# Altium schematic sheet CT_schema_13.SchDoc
size 564 x 458 mm
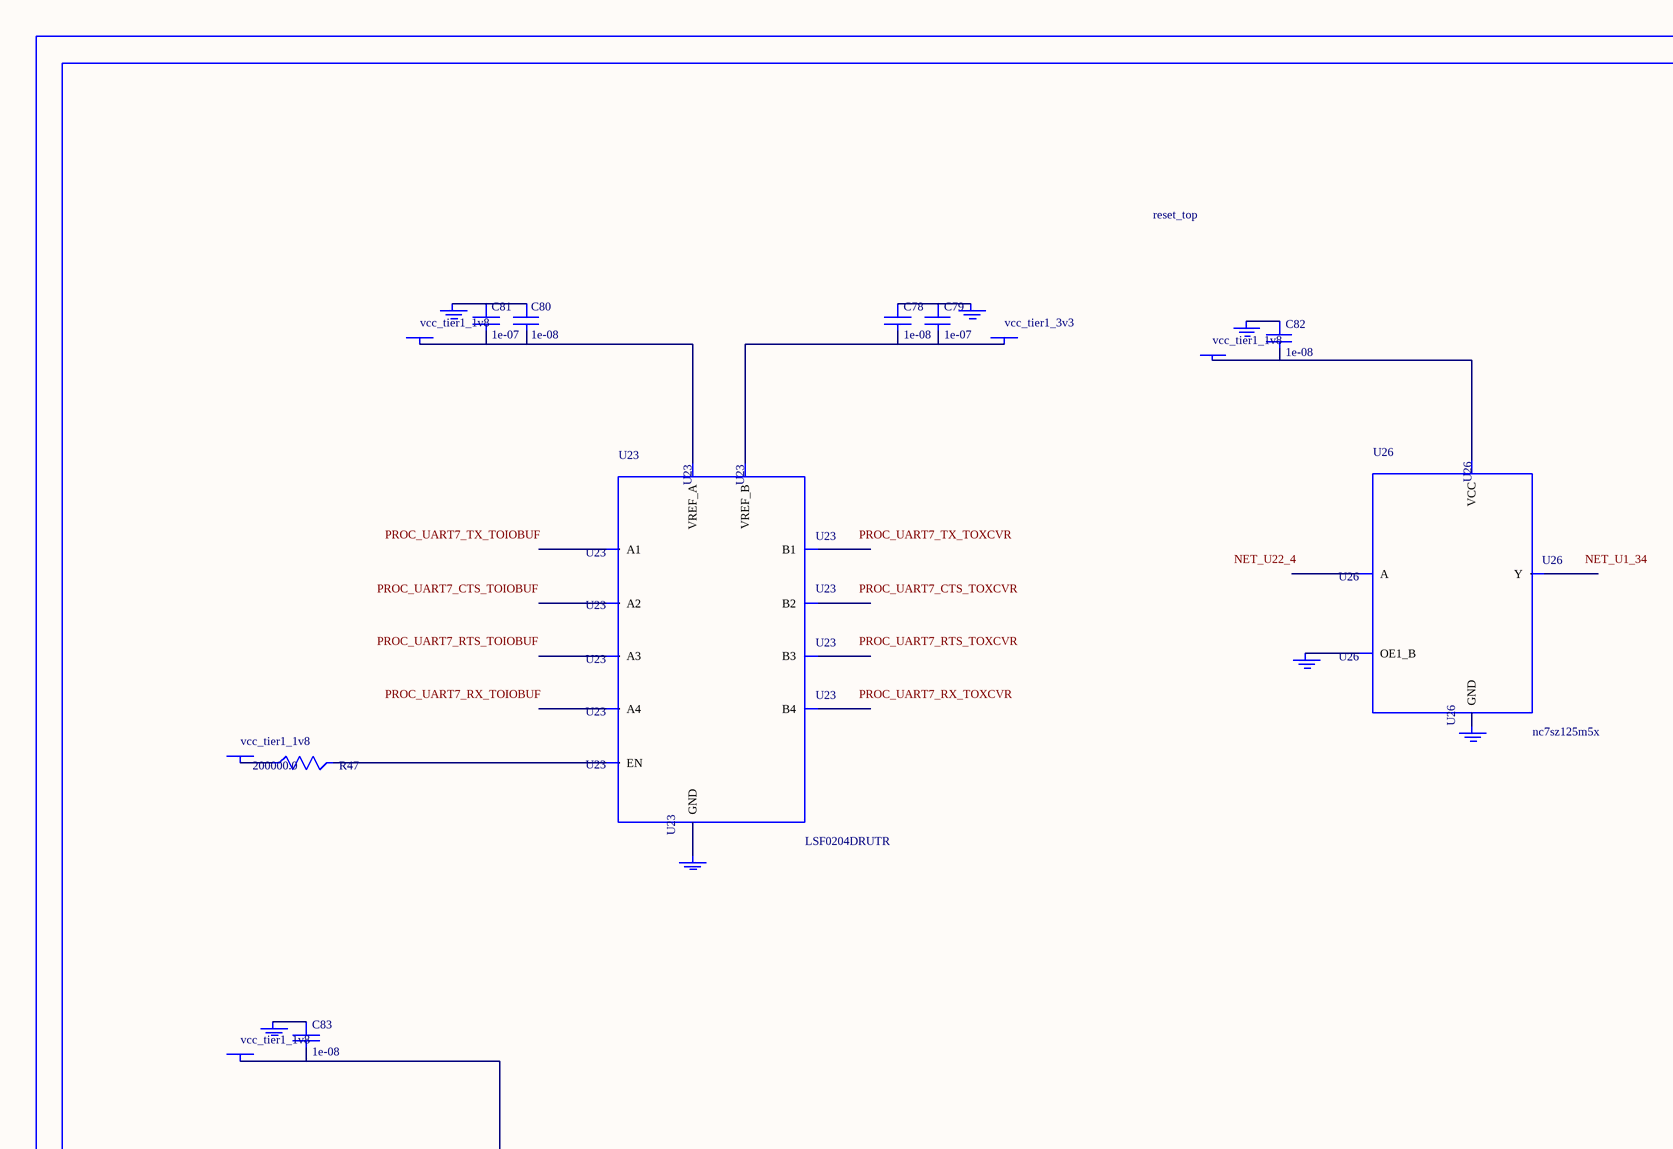
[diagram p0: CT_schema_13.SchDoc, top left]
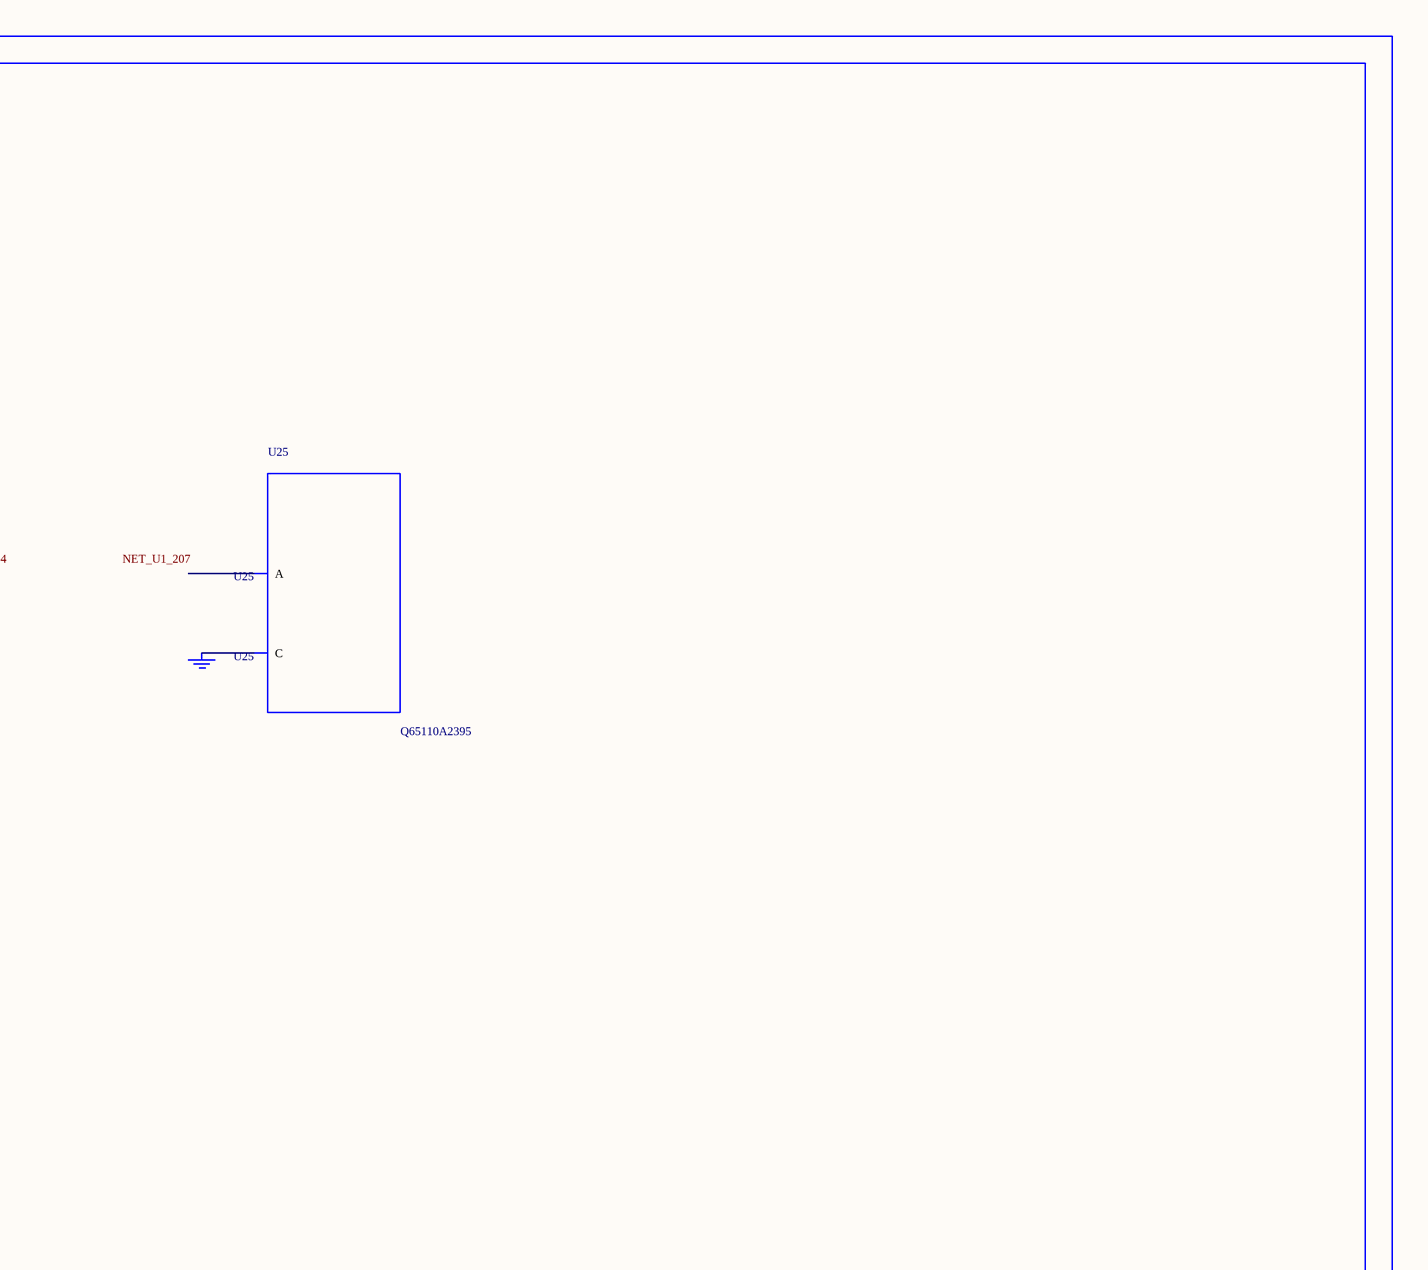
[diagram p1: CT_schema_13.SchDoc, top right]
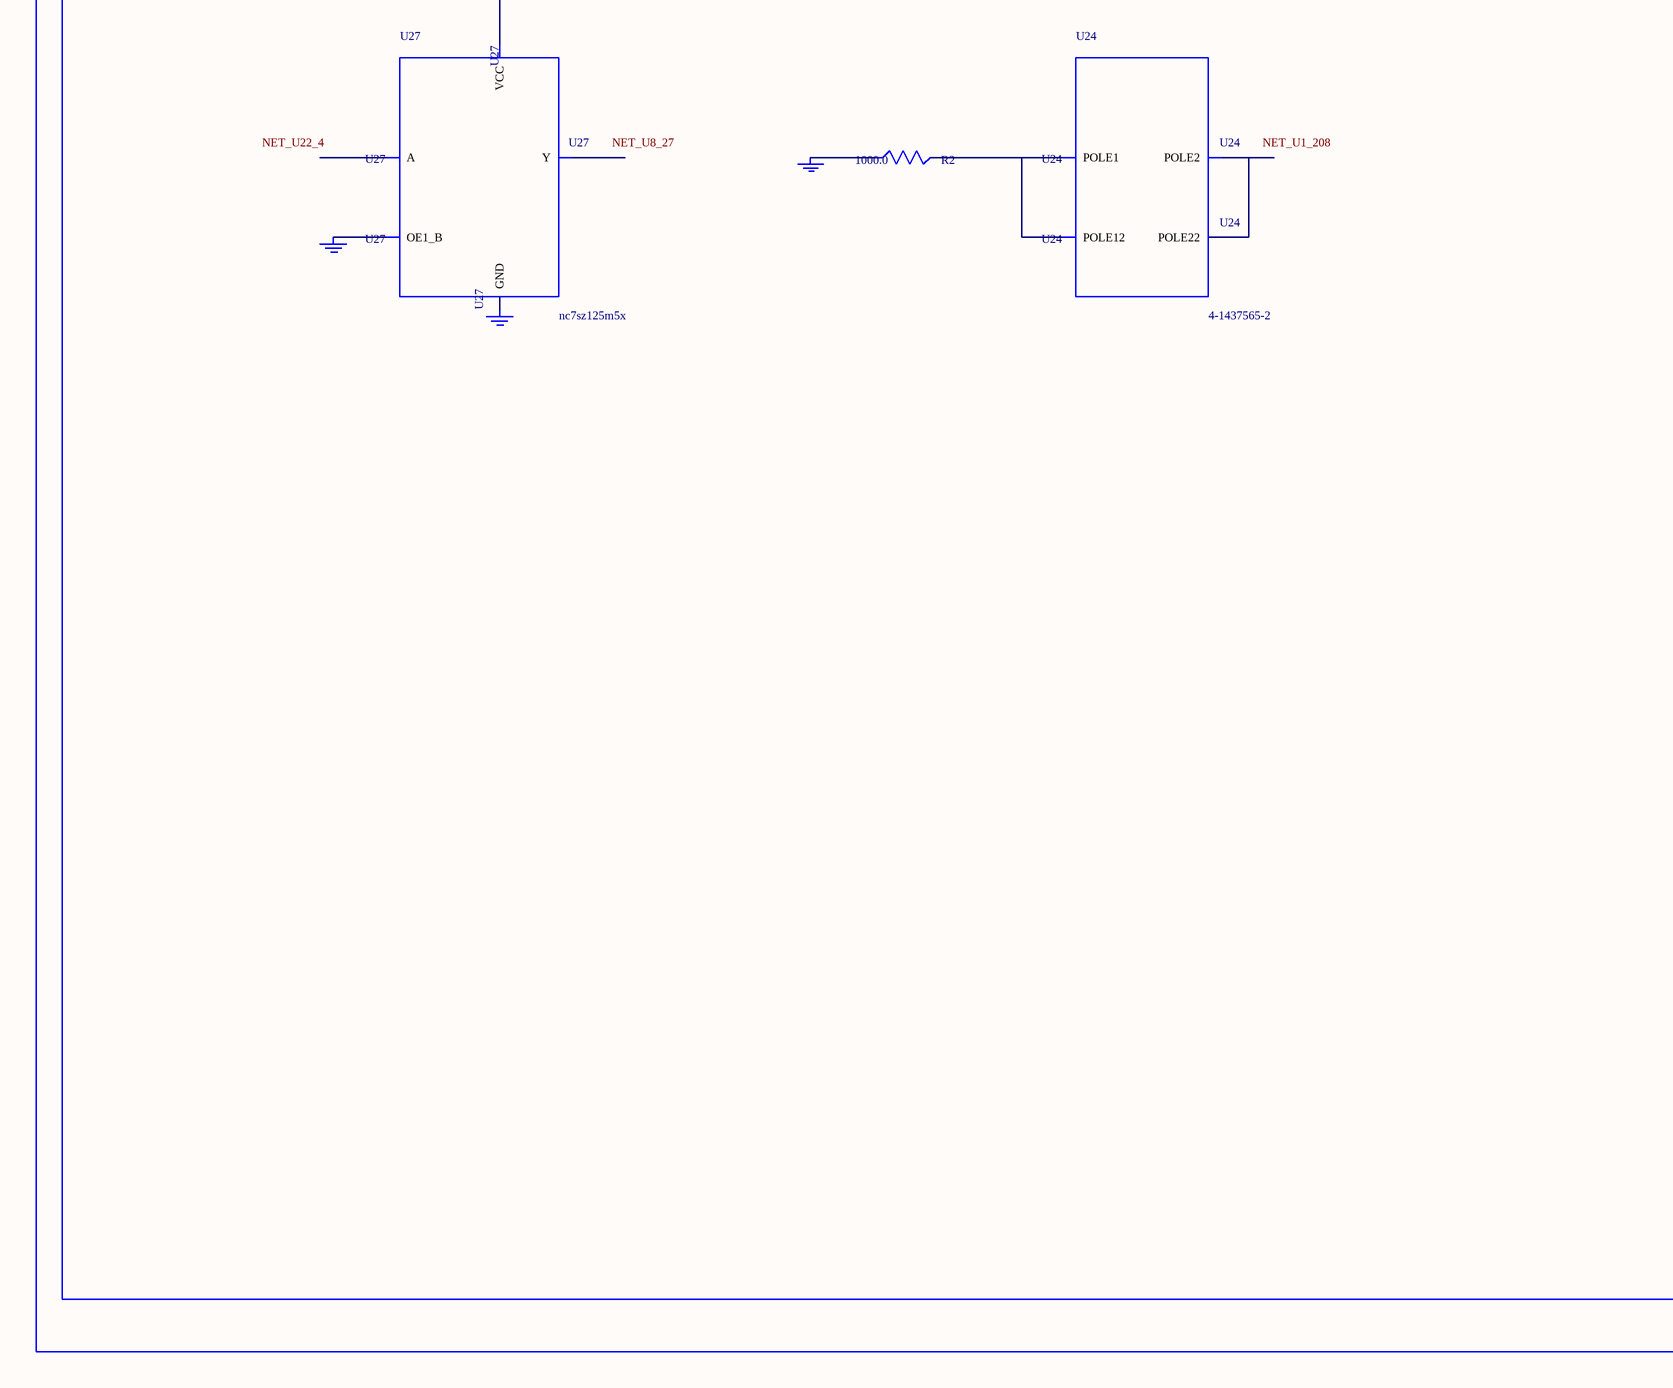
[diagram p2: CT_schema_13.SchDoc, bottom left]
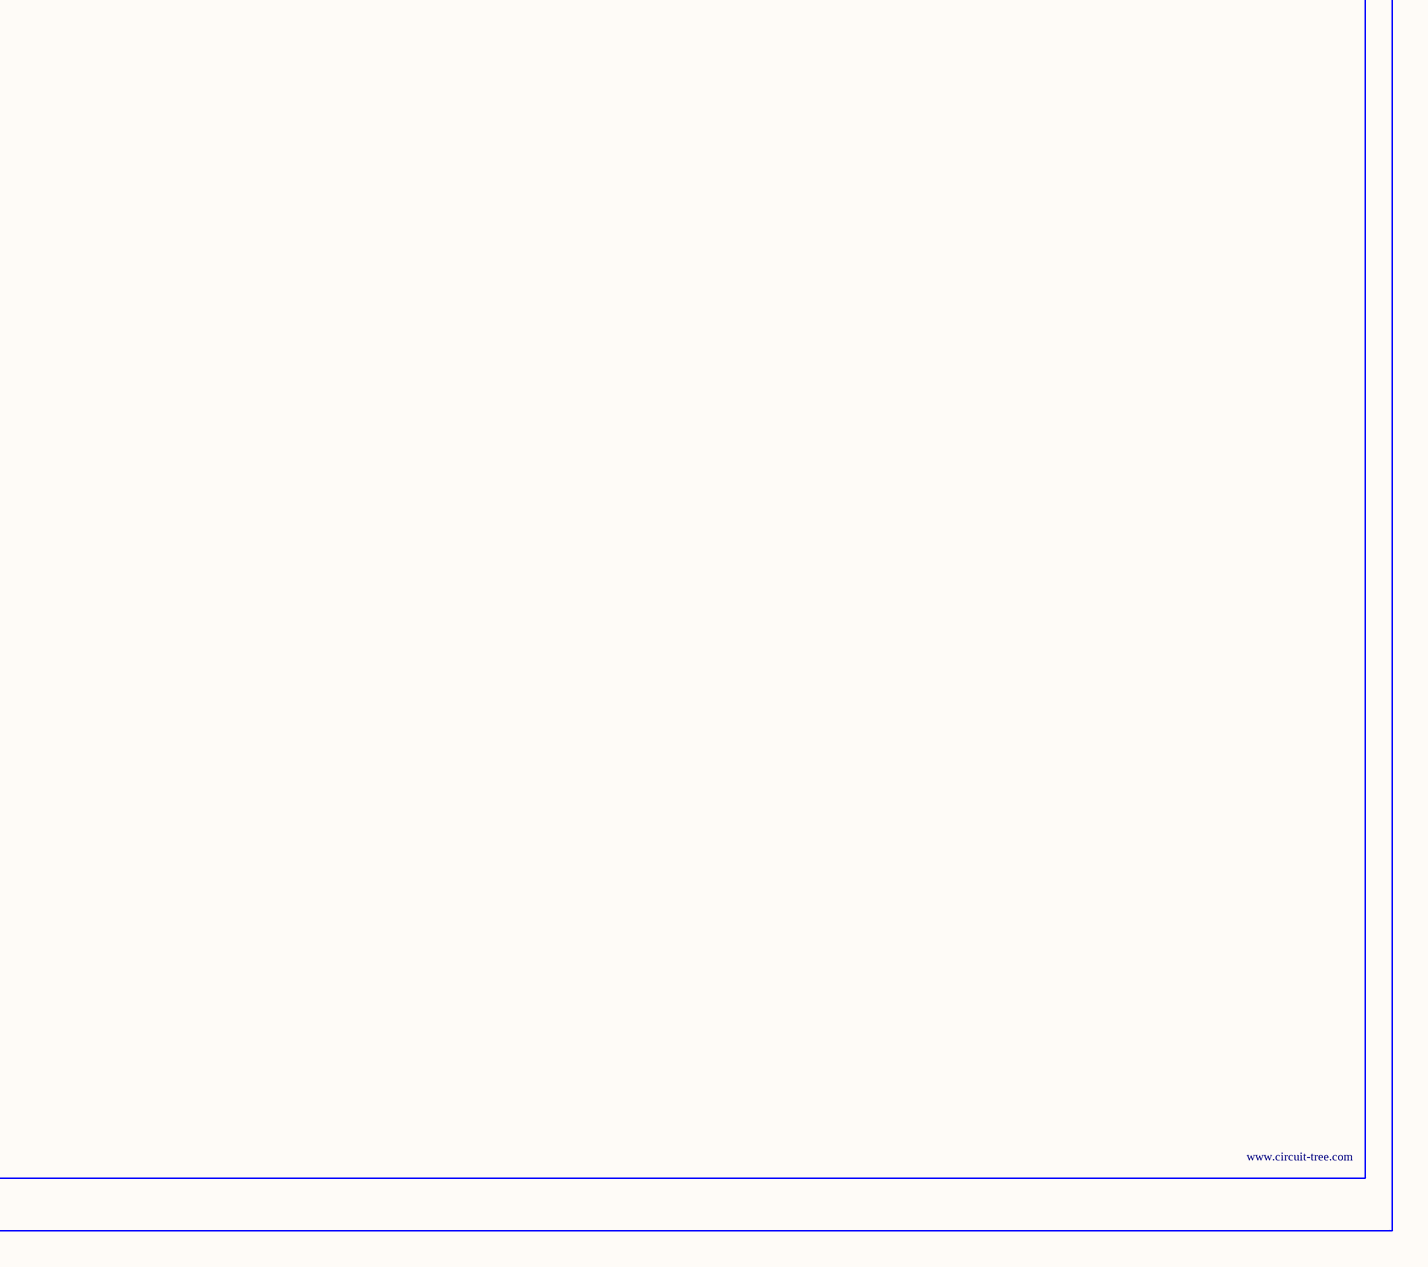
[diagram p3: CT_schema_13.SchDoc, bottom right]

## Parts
BORDER12  (no value)
C78  1e-08  [C0402]
C79  1e-07  [C0402]
C80  1e-08  [C0402]
C81  1e-07  [C0402]
C82  1e-08  [C0402]
C83  1e-08  [C0402]
GND_INSTANCE_12_0  (no value)
GND_INSTANCE_12_1  (no value)
GND_INSTANCE_12_2  (no value)
GND_INSTANCE_12_3  (no value)
GND_INSTANCE_12_4  (no value)
GND_INSTANCE_12_5  (no value)
GND_INSTANCE_12_6  (no value)
GND_INSTANCE_12_7  (no value)
GND_INSTANCE_12_8  (no value)
GND_INSTANCE_12_9  (no value)
GND_INSTANCE_12_10  (no value)
POWER_INSTANCE_12_0  vcc_tier1_1v8
POWER_INSTANCE_12_1  vcc_tier1_3v3
POWER_INSTANCE_12_2  vcc_tier1_1v8
POWER_INSTANCE_12_3  vcc_tier1_1v8
POWER_INSTANCE_12_4  vcc_tier1_1v8
R2  1000.0  [R0603]
R47  200000.0  [R0603]
U23  LSF0204DRUTR  [RUT0012A]
U24  4-1437565-2  [SW_4-1437565-2]
U25  Q65110A2395  [LGM67K-G1J2-24-Z]
U26  nc7sz125m5x  [NC7SZ125M5X]
U27  nc7sz125m5x  [NC7SZ125M5X]

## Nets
NetC78_1: C78.1 C79.1 GND_INSTANCE_12_1.0(GND)
NetC78_2: C78.2 C79.2 POWER_INSTANCE_12_1.0(PWR) U23.11(VREF_B)
NetC80_1: C80.1 C81.1 GND_INSTANCE_12_0.0(GND)
NetC80_2: C80.2 C81.2 POWER_INSTANCE_12_0.0(PWR) U23.1(VREF_A)
NetC82_1: C82.1 GND_INSTANCE_12_5.0(GND)
NetC82_2: C82.2 POWER_INSTANCE_12_3.0(PWR) U26.5(VCC)
NetC83_1: C83.1 GND_INSTANCE_12_8.0(GND)
NetC83_2: C83.2 POWER_INSTANCE_12_4.0(PWR) U27.5(VCC)
NetGND_INSTANCE_12_2_0: GND_INSTANCE_12_2.0(GND) U23.6(GND)
NetGND_INSTANCE_12_3_0: GND_INSTANCE_12_3.0(GND) R2.1
NetGND_INSTANCE_12_4_0: GND_INSTANCE_12_4.0(GND) U25.C
NetGND_INSTANCE_12_6_0: GND_INSTANCE_12_6.0(GND) U26.1(OE1_B)
NetGND_INSTANCE_12_7_0: GND_INSTANCE_12_7.0(GND) U26.3(GND)
NetGND_INSTANCE_12_9_0: GND_INSTANCE_12_9.0(GND) U27.1(OE1_B)
NetGND_INSTANCE_12_10_0: GND_INSTANCE_12_10.0(GND) U27.3(GND)
NetPOWER_INSTANCE_12_2_0: POWER_INSTANCE_12_2.0(PWR) R47.1
NetR2_2: R2.2 U24.1(POLE1) U24.2(POLE12)
NetR47_2: R47.2 U23.12(EN)
NetU24_3: U24.3(POLE2) U24.4(POLE22)

Not connected (* = marked no-connect by the designer): U23 2(A1) 3(A2) 4(A3) 5(A4) 7(B4) 8(B3) 9(B2) 10(B1); U25 A; U26 2(A) 4(Y); U27 2(A) 4(Y)

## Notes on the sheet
- Labels drawn without touching a wire or pin: NET_U1_34, NET_U1_207, NET_U1_208, NET_U8_27, NET_U22_4, PROC_UART7_CTS_TOIOBUF, PROC_UART7_CTS_TOXCVR, PROC_UART7_RTS_TOIOBUF, PROC_UART7_RTS_TOXCVR, PROC_UART7_RX_TOIOBUF, PROC_UART7_RX_TOXCVR, PROC_UART7_TX_TOIOBUF, PROC_UART7_TX_TOXCVR

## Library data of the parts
BORDER12 = BORDER_PAGE12
C78 C80 C82 C83 = C0402C103K3RAC
C79 C81 = C0402C104K3RACTU
GND_INSTANCE_12_0-GND_INSTANCE_12_10 = GND
POWER_INSTANCE_12_0-POWER_INSTANCE_12_4 = PWR
R2 = RC0603JR-071KL
R47 = RC0603JR-07200KL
